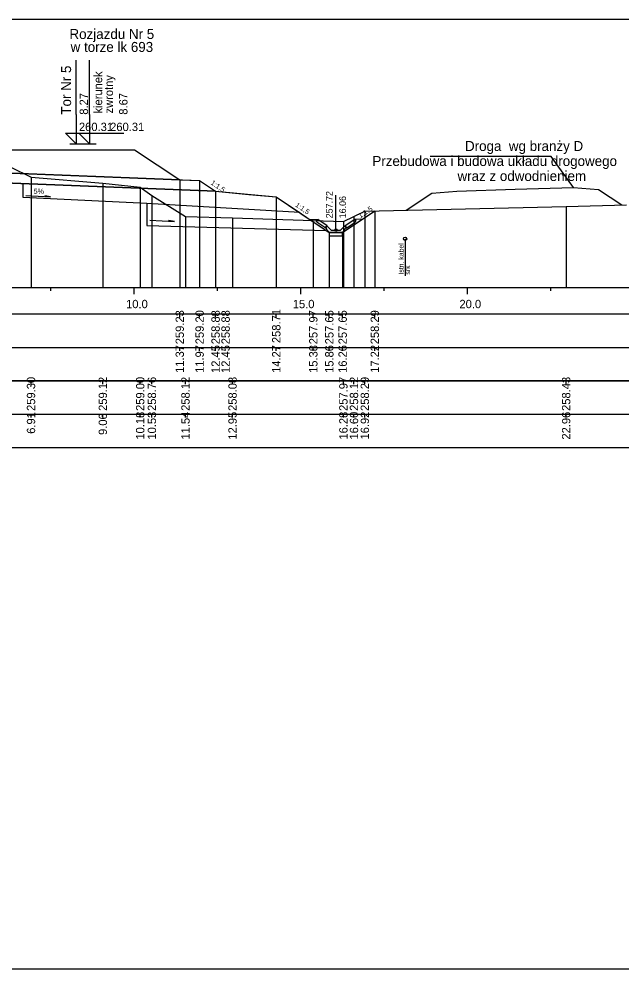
# Model space of a CAD drawing. Extents: x 6516023 to 6560129, y 5513077 to 5529206.
# Drawn here: x 6516684.76 to 6516702.85, y 5514484.66 to 5514513.16 of the extents above; entities that cross this region are included whole.
import ezdxf

# ---------------------------------------------------------------- set-up
doc = ezdxf.new("R2010")
doc.units = 0
for name, color, linetype in [('IR_default', 7, 'Continuous'), ('TOR_PRZEK_P-inne branze', 7, 'Continuous'), ('TOR_PRZEK_P-kable', 7, 'Continuous'), ('TOR_PRZEK_P-komponent', 7, 'Continuous'), ('TOR_PRZEK_P-odwodnienie', 7, 'Continuous'), ('TOR_PRZEK_P-opisy', 7, 'Continuous'), ('TOR_PRZEK_P-schodkowanie+wymiana', 7, 'Continuous'), ('TOR_PRZEK_P-tabelka istniejace', 7, 'Continuous'), ('TOR_PRZEK_P-tabelka projektowane', 7, 'Continuous'), ('TOR_PRZEK_P-teren istniejacy', 7, 'Continuous'), ('TOR_PRZEK_P-tory projektowane', 7, 'Continuous'), ('TOR_PRZEK_P-uklad odniesienia', 7, 'Continuous'), ('TOR_PRZEK_P-warstwa ochronna I', 7, 'Continuous'), ('TOR_PRZEK_P-warstwa ochronna II', 7, 'Continuous'), ('TOR_PS_T-skarpy projektowane', 7, 'Continuous'), ('TOR_RAMKI-ramka+tabelka 1', 7, 'Continuous')]:
    doc.layers.add(name, color=color, linetype=linetype)

msp = doc.modelspace()

# ---------------------------------------------------------------- linework, layer by layer
at = {"layer": 'IR_default'}
msp.add_lwpolyline([(6516684.73, 5514509.235), (6516686.494, 5514509.235), (6516688.23, 5514509.235), (6516688.911, 5514508.781), (6516689.584, 5514508.333), (6516689.886, 5514508.32), (6516690.18, 5514508.309), (6516690.502, 5514508.094), (6516690.659, 5514507.99), (6516691.651, 5514507.895), (6516692.48, 5514507.817), (6516693.041, 5514507.442), (6516693.59, 5514507.076), (6516693.832, 5514506.915), (6516694.07, 5514506.756), (6516694.272, 5514506.756), (6516694.47, 5514506.756), (6516694.848, 5514507.008), (6516695.22, 5514507.256), (6516695.434, 5514507.398)], dxfattribs=at)
at = {"layer": 'TOR_PRZEK_P-inne branze'}
for p, q in [((6516700.72, 5514509.035), (6516697.096, 5514509.035)), ((6516701.396, 5514508.101), (6516700.72, 5514509.035))]:
    msp.add_line(p, q, dxfattribs=at)
msp.add_lwpolyline([(6516696.373, 5514507.421), (6516697.146, 5514507.936), (6516697.896, 5514507.996), (6516699.646, 5514508.048), (6516701.396, 5514508.101), (6516702.146, 5514508.041), (6516702.841, 5514507.578)], dxfattribs=at)
at = {"layer": 'TOR_PRZEK_P-kable'}
msp.add_line((6516696.344, 5514506.562), (6516696.344, 5514505.452), dxfattribs=at)
msp.add_circle((6516696.344, 5514506.562), 0.05, dxfattribs=at)
at = {"layer": 'TOR_PRZEK_P-komponent'}
for points in [[(6516671.963, 5514509.235), (6516673.713, 5514509.235), (6516672.659, 5514509.235), (6516675.463, 5514509.235), (6516676.463, 5514509.235), (6516678.213, 5514509.235), (6516679.963, 5514509.235), (6516680.513, 5514509.236), (6516682.263, 5514509.236), (6516684.013, 5514509.236), (6516684.73, 5514509.235), (6516688.23, 5514509.235), (6516689.584, 5514508.333), (6516680.238, 5514508.706), (6516670.591, 5514508.32)], [(6516670.013, 5514508.297), (6516680.238, 5514508.706), (6516690.18, 5514508.309), (6516690.659, 5514507.99), (6516680.238, 5514508.406), (6516669.534, 5514507.978)]]:
    msp.add_lwpolyline(points, close=True, dxfattribs=at)
at = {"layer": 'TOR_PRZEK_P-odwodnienie'}
for p, q in [((6516694.27, 5514506.826), (6516694.27, 5514507.87)), ((6516693.961, 5514506.886), (6516693.7, 5514507.06)), ((6516694.006, 5514506.952), (6516693.725, 5514507.139)), ((6516693.973, 5514506.902), (6516693.961, 5514506.886)), ((6516693.963, 5514506.921), (6516694.01, 5514506.945)), ((6516694.006, 5514506.952), (6516693.997, 5514506.94)), ((6516694.13, 5514506.826), (6516694.01, 5514506.945)), ((6516694.41, 5514506.826), (6516694.53, 5514506.945)), ((6516694.53, 5514506.945), (6516694.578, 5514506.921)), ((6516694.535, 5514506.952), (6516694.815, 5514507.139)), ((6516694.535, 5514506.952), (6516694.543, 5514506.94)), ((6516694.568, 5514506.902), (6516694.579, 5514506.886)), ((6516694.579, 5514506.886), (6516694.841, 5514507.06)), ((6516694.08, 5514506.756), (6516694.46, 5514506.756)), ((6516694.13, 5514506.826), (6516694.41, 5514506.826))]:
    msp.add_line(p, q, dxfattribs=at)
for points in [[(6516693.479, 5514507.151), (6516693.725, 5514507.139)], [(6516693.675, 5514507.112), (6516693.725, 5514507.139)], [(6516693.675, 5514507.112), (6516693.7, 5514507.06)], [(6516693.997, 5514506.94), (6516693.962, 5514506.921)], [(6516693.962, 5514506.921), (6516693.973, 5514506.902)], [(6516694.01, 5514506.826), (6516693.963, 5514506.921)], [(6516694.53, 5514506.826), (6516694.578, 5514506.921)], [(6516694.543, 5514506.94), (6516694.579, 5514506.921)], [(6516694.579, 5514506.921), (6516694.568, 5514506.902)], [(6516695.062, 5514507.151), (6516694.815, 5514507.139)], [(6516694.866, 5514507.112), (6516694.815, 5514507.139)], [(6516694.866, 5514507.112), (6516694.841, 5514507.06)], [(6516694.08, 5514506.756), (6516694.01, 5514506.826)], [(6516694.07, 5514506.756), (6516694.07, 5514506.757), (6516694.07, 5514506.756), (6516694.07, 5514506.756), (6516694.07, 5514506.756), (6516694.071, 5514506.756), (6516694.07, 5514506.756), (6516694.071, 5514506.757)], [(6516694.47, 5514506.756), (6516694.07, 5514506.756), (6516694.07, 5514506.656), (6516694.47, 5514506.656), (6516694.47, 5514506.756)], [(6516694.46, 5514506.756), (6516694.53, 5514506.826)], [(6516694.47, 5514506.756), (6516694.47, 5514506.757), (6516694.47, 5514506.756), (6516694.47, 5514506.756), (6516694.47, 5514506.756), (6516694.471, 5514506.756), (6516694.47, 5514506.756), (6516694.471, 5514506.757)]]:
    msp.add_lwpolyline(points, dxfattribs=at)
msp.add_circle((6516694.27, 5514506.826), 0.035, dxfattribs=at)
at = {"layer": 'TOR_PRZEK_P-schodkowanie+wymiana'}
for p, q in [((6516684.876, 5514508.221), (6516684.876, 5514507.815)), ((6516684.876, 5514507.815), (6516688.593, 5514507.629)), ((6516688.593, 5514507.629), (6516688.593, 5514506.963)), ((6516688.593, 5514507.629), (6516693.182, 5514507.357)), ((6516688.593, 5514506.963), (6516693.987, 5514506.812))]:
    msp.add_line(p, q, dxfattribs=at)
at = {"layer": 'TOR_PRZEK_P-tabelka istniejace'}
for p, q in [((6516685.122, 5514502.206), (6516685.122, 5514502.306)), ((6516687.277, 5514502.206), (6516687.277, 5514502.306)), ((6516688.397, 5514502.206), (6516688.397, 5514502.306)), ((6516688.748, 5514502.206), (6516688.748, 5514502.306)), ((6516689.756, 5514502.206), (6516689.756, 5514502.306)), ((6516691.167, 5514502.206), (6516691.167, 5514502.306)), ((6516694.492, 5514502.206), (6516694.492, 5514502.306)), ((6516694.81, 5514502.206), (6516694.81, 5514502.306)), ((6516695.136, 5514502.206), (6516695.136, 5514502.306)), ((6516701.174, 5514502.206), (6516701.174, 5514502.306)), ((6516637.163, 5514501.306), (6516720.963, 5514501.306)), ((6516685.122, 5514501.206), (6516685.122, 5514501.306)), ((6516687.277, 5514501.206), (6516687.277, 5514501.306)), ((6516688.397, 5514501.206), (6516688.397, 5514501.306)), ((6516688.748, 5514501.206), (6516688.748, 5514501.306)), ((6516689.756, 5514501.206), (6516689.756, 5514501.306)), ((6516691.167, 5514501.206), (6516691.167, 5514501.306)), ((6516694.492, 5514501.206), (6516694.492, 5514501.306)), ((6516694.81, 5514501.206), (6516694.81, 5514501.306)), ((6516695.136, 5514501.206), (6516695.136, 5514501.306)), ((6516701.174, 5514501.206), (6516701.174, 5514501.306))]:
    msp.add_line(p, q, dxfattribs=at)
for points in [[(6516685.122, 5514508.407), (6516685.122, 5514505.306), (6516685.122, 5514505.176), (6516685.122, 5514505.106)], [(6516687.277, 5514508.227), (6516687.277, 5514505.306), (6516687.277, 5514505.176), (6516687.277, 5514505.106)], [(6516688.397, 5514508.108), (6516688.397, 5514505.306), (6516688.397, 5514505.176), (6516688.397, 5514505.106)], [(6516688.748, 5514507.864), (6516688.748, 5514505.306), (6516688.748, 5514505.176), (6516688.748, 5514505.106)], [(6516701.174, 5514507.535), (6516701.174, 5514505.306), (6516701.174, 5514505.176), (6516701.174, 5514505.106)], [(6516689.756, 5514507.231), (6516689.756, 5514505.306), (6516689.756, 5514505.176), (6516689.756, 5514505.106)], [(6516691.167, 5514507.188), (6516691.167, 5514505.306), (6516691.167, 5514505.176), (6516691.167, 5514505.106)], [(6516694.81, 5514507.228), (6516694.81, 5514505.306), (6516694.81, 5514505.176), (6516694.81, 5514505.106)], [(6516695.136, 5514507.391), (6516695.136, 5514505.306), (6516695.136, 5514505.176), (6516695.136, 5514505.106)], [(6516694.492, 5514507.078), (6516694.492, 5514505.306), (6516694.492, 5514505.176), (6516694.492, 5514505.106)]]:
    msp.add_lwpolyline(points, dxfattribs=at)
msp.add_lwpolyline([(6516637.163, 5514502.306), (6516637.163, 5514500.306), (6516720.963, 5514500.306), (6516720.963, 5514502.306)], close=True, dxfattribs=at)
at = {"layer": 'TOR_PRZEK_P-tabelka projektowane'}
for p, q in [((6516689.584, 5514504.206), (6516689.584, 5514504.306)), ((6516690.18, 5514504.206), (6516690.18, 5514504.306)), ((6516690.659, 5514504.206), (6516690.659, 5514504.306)), ((6516690.659, 5514504.206), (6516690.659, 5514504.306)), ((6516692.48, 5514504.206), (6516692.48, 5514504.306)), ((6516693.59, 5514504.206), (6516693.59, 5514504.306)), ((6516694.07, 5514504.206), (6516694.07, 5514504.306)), ((6516694.47, 5514504.206), (6516694.47, 5514504.306)), ((6516695.434, 5514504.206), (6516695.434, 5514504.306)), ((6516637.163, 5514503.306), (6516720.963, 5514503.306)), ((6516689.584, 5514503.206), (6516689.584, 5514503.306)), ((6516690.18, 5514503.206), (6516690.18, 5514503.306)), ((6516690.659, 5514503.206), (6516690.659, 5514503.306)), ((6516690.659, 5514503.206), (6516690.659, 5514503.306)), ((6516692.48, 5514503.206), (6516692.48, 5514503.306)), ((6516693.59, 5514503.206), (6516693.59, 5514503.306)), ((6516694.07, 5514503.206), (6516694.07, 5514503.306)), ((6516694.47, 5514503.206), (6516694.47, 5514503.306)), ((6516695.434, 5514503.206), (6516695.434, 5514503.306))]:
    msp.add_line(p, q, dxfattribs=at)
for points in [[(6516689.584, 5514508.333), (6516689.584, 5514505.306), (6516689.584, 5514505.176), (6516689.584, 5514505.106)], [(6516690.18, 5514508.309), (6516690.18, 5514505.306), (6516690.18, 5514505.176), (6516690.18, 5514505.106)], [(6516690.659, 5514507.99), (6516690.659, 5514505.306), (6516690.659, 5514505.176), (6516690.659, 5514505.106)], [(6516692.48, 5514507.817), (6516692.48, 5514505.306), (6516692.48, 5514505.176), (6516692.48, 5514505.106)], [(6516695.434, 5514507.398), (6516695.434, 5514505.306), (6516695.434, 5514505.176), (6516695.434, 5514505.106)], [(6516693.59, 5514507.076), (6516693.59, 5514505.306), (6516693.59, 5514505.176), (6516693.59, 5514505.106)], [(6516694.07, 5514506.756), (6516694.07, 5514505.306), (6516694.07, 5514505.176), (6516694.07, 5514505.106)], [(6516694.47, 5514506.756), (6516694.47, 5514505.306), (6516694.47, 5514505.176), (6516694.47, 5514505.106)]]:
    msp.add_lwpolyline(points, dxfattribs=at)
msp.add_lwpolyline([(6516637.163, 5514504.306), (6516637.163, 5514502.306), (6516720.963, 5514502.306), (6516720.963, 5514504.306)], close=True, dxfattribs=at)
at = {"layer": 'TOR_PRZEK_P-teren istniejacy'}
msp.add_lwpolyline([(6516666.714, 5514508.593), (6516667.476, 5514508.985), (6516668.722, 5514509.029), (6516670.582, 5514509.069), (6516670.981, 5514508.881), (6516671.437, 5514508.659), (6516671.878, 5514508.648), (6516672.182, 5514508.648), (6516672.567, 5514508.862), (6516673.144, 5514509.196), (6516677.725, 5514509.124), (6516684.073, 5514508.97), (6516684.52, 5514508.709), (6516685.122, 5514508.407), (6516687.277, 5514508.227), (6516688.397, 5514508.108), (6516688.748, 5514507.864), (6516689.756, 5514507.231), (6516691.167, 5514507.188), (6516694.492, 5514507.078), (6516694.81, 5514507.228), (6516695.136, 5514507.391), (6516701.174, 5514507.535), (6516702.986, 5514507.581)], dxfattribs=at)
at = {"layer": 'TOR_PRZEK_P-tory projektowane'}
for p, q in [((6516686.48, 5514510.293), (6516686.48, 5514511.925)), ((6516686.88, 5514510.293), (6516686.88, 5514511.925)), ((6516686.48, 5514510.293), (6516686.48, 5514509.415)), ((6516686.88, 5514510.293), (6516686.88, 5514509.415)), ((6516686.48, 5514509.415), (6516686.161, 5514509.734)), ((6516686.161, 5514509.734), (6516687.505, 5514509.734)), ((6516686.88, 5514509.415), (6516686.561, 5514509.734)), ((6516686.561, 5514509.734), (6516687.905, 5514509.734)), ((6516686.288, 5514509.415), (6516686.672, 5514509.415)), ((6516686.688, 5514509.415), (6516687.072, 5514509.415))]:
    msp.add_line(p, q, dxfattribs=at)
at = {"layer": 'TOR_PRZEK_P-uklad odniesienia'}
for p, q in [((6516640.963, 5514505.106), (6516720.963, 5514505.106)), ((6516685.713, 5514505.006), (6516685.713, 5514505.106)), ((6516688.213, 5514504.906), (6516688.213, 5514505.106)), ((6516690.713, 5514505.006), (6516690.713, 5514505.106)), ((6516693.213, 5514504.906), (6516693.213, 5514505.106)), ((6516695.713, 5514505.006), (6516695.713, 5514505.106)), ((6516698.213, 5514504.906), (6516698.213, 5514505.106)), ((6516700.713, 5514505.006), (6516700.713, 5514505.106))]:
    msp.add_line(p, q, dxfattribs=at)
at = {"layer": 'TOR_PRZEK_P-warstwa ochronna I'}
msp.add_lwpolyline([(6516669.534, 5514507.978), (6516680.238, 5514508.406), (6516690.659, 5514507.99)], dxfattribs=at)
at = {"layer": 'TOR_PRZEK_P-warstwa ochronna II'}
msp.add_lwpolyline([(6516659.75, 5514507.819), (6516660.689, 5514507.838), (6516662.146, 5514506.867), (6516662.546, 5514506.867), (6516662.951, 5514507.137), (6516663.713, 5514507.645), (6516669.534, 5514507.978), (6516670.013, 5514508.297), (6516670.591, 5514508.32), (6516678.963, 5514508.655), (6516680.238, 5514508.706), (6516681.513, 5514508.656), (6516689.584, 5514508.333), (6516690.18, 5514508.309), (6516690.659, 5514507.99), (6516692.48, 5514507.817), (6516693.59, 5514507.076), (6516694.07, 5514506.756), (6516694.47, 5514506.756), (6516695.434, 5514507.398)], dxfattribs=at)
at = {"layer": 'TOR_PS_T-skarpy projektowane'}
for points in [[(6516684.969, 5514507.859), (6516685.704, 5514507.82), (6516685.532, 5514507.85)], [(6516688.687, 5514507.123), (6516689.422, 5514507.083), (6516689.249, 5514507.114)]]:
    msp.add_lwpolyline(points, dxfattribs=at)
at = {"layer": 'TOR_RAMKI-ramka+tabelka 1'}
msp.add_lwpolyline([(6516634.513, 5514513.156), (6516882.013, 5514513.156), (6516882.013, 5514484.656), (6516634.513, 5514484.656)], close=True, dxfattribs=at)

# ---------------------------------------------------------------- texts
at = {"layer": 'TOR_PRZEK_P-inne branze'}
for s, p in [('Droga  wg branży D', (6516698.14, 5514509.196)), ('Przebudowa i budowa układu drogowego', (6516695.362, 5514508.746)), ('wraz z odwodnieniem ', (6516697.915, 5514508.296))]:
    msp.add_text(s, height=0.3, dxfattribs=at).set_placement(p)
at = {"layer": 'TOR_PRZEK_P-kable'}
for s, height, p in [('Istn. kabel', 0.14999, (6516696.299, 5514505.488)), ('srk', 0.15, (6516696.493, 5514505.488))]:
    msp.add_text(s, height=height, rotation=90.0511, dxfattribs=at).set_placement(p)
at = {"layer": 'TOR_PRZEK_P-odwodnienie'}
for s, p in [('257.72', (6516694.17, 5514507.176)), ('16.06', (6516694.57, 5514507.176))]:
    msp.add_text(s, height=0.2, rotation=90, dxfattribs=at).set_placement(p)
at = {"layer": 'TOR_PRZEK_P-opisy'}
for rotation, p in [(325.9299, (6516690.498, 5514508.208)), (325.9299, (6516693.034, 5514507.544)), (34.0701, (6516695.003, 5514507.171))]:
    msp.add_text('1:1,5', height=0.15, rotation=rotation, dxfattribs=at).set_placement(p)
at = {"layer": 'TOR_PRZEK_P-tabelka istniejace'}
for s, p in [('259.30', (6516685.247, 5514501.398)), ('259.12', (6516687.402, 5514501.4)), ('259.00', (6516688.522, 5514501.398)), ('258.76', (6516688.873, 5514501.398)), ('258.12', (6516689.881, 5514501.4)), ('258.08', (6516691.292, 5514501.398)), ('257.97', (6516694.617, 5514501.398)), ('258.12', (6516694.935, 5514501.4)), ('258.29', (6516695.261, 5514501.398)), ('258.43', (6516701.299, 5514501.398)), ('6.91', (6516685.247, 5514500.712)), ('9.06', (6516687.402, 5514500.677)), ('10.18', (6516688.522, 5514500.538)), ('10.53', (6516688.873, 5514500.538)), ('11.54', (6516689.881, 5514500.539)), ('12.95', (6516691.292, 5514500.537)), ('16.28', (6516694.617, 5514500.538)), ('16.60', (6516694.935, 5514500.538)), ('16.92', (6516695.261, 5514500.54)), ('22.96', (6516701.299, 5514500.538))]:
    msp.add_text(s, height=0.25, rotation=90, dxfattribs=at).set_placement(p)
at = {"layer": 'TOR_PRZEK_P-tabelka projektowane'}
for s, p in [('259.23', (6516689.709, 5514503.398)), ('259.20', (6516690.305, 5514503.398)), ('258.88', (6516690.784, 5514503.398)), ('258.88', (6516691.084, 5514503.398)), ('258.71', (6516692.605, 5514503.433)), ('257.97', (6516693.715, 5514503.398)), ('257.65', (6516694.195, 5514503.397)), ('257.65', (6516694.595, 5514503.397)), ('258.29', (6516695.559, 5514503.398)), ('11.37', (6516689.709, 5514502.538)), ('11.97', (6516690.305, 5514502.538)), ('12.45', (6516690.784, 5514502.537)), ('12.45', (6516691.084, 5514502.537)), ('14.27', (6516692.605, 5514502.538)), ('15.38', (6516693.715, 5514502.538)), ('15.86', (6516694.195, 5514502.538)), ('16.26', (6516694.595, 5514502.538)), ('17.22', (6516695.559, 5514502.54))]:
    msp.add_text(s, height=0.25, rotation=90, dxfattribs=at).set_placement(p)
at = {"layer": 'TOR_PRZEK_P-tory projektowane'}
for s, height, rotation, p in [('Rozjazdu Nr 5', 0.3, 360, (6516686.276, 5514512.556)), ('w torze lk 693', 0.3, 360, (6516686.311, 5514512.168)), ('Tor Nr 5', 0.3, 90, (6516686.325, 5514510.287)), ('kierunek', 0.25, 90, (6516687.257, 5514510.321)), ('zwrotny', 0.25, 90, (6516687.581, 5514510.321)), ('8.27', 0.25, 90, (6516686.83, 5514510.285)), ('8.67', 0.25, 90, (6516688.016, 5514510.285))]:
    msp.add_text(s, height=height, rotation=rotation, dxfattribs=at).set_placement(p)
for p in [(6516686.56, 5514509.795), (6516687.496, 5514509.795)]:
    msp.add_text('260.31', height=0.25, dxfattribs=at).set_placement(p)
at = {"layer": 'TOR_PRZEK_P-uklad odniesienia'}
for s, p in [('10.0', (6516687.974, 5514504.481)), ('15.0', (6516692.974, 5514504.481)), ('20.0', (6516697.974, 5514504.481))]:
    msp.add_text(s, height=0.25, dxfattribs=at).set_placement(p)
at = {"layer": 'TOR_PS_T-skarpy projektowane'}
msp.add_text('5%', height=0.1545, dxfattribs=at).set_placement((6516685.201, 5514507.911))

doc.saveas('drawing.dxf')
